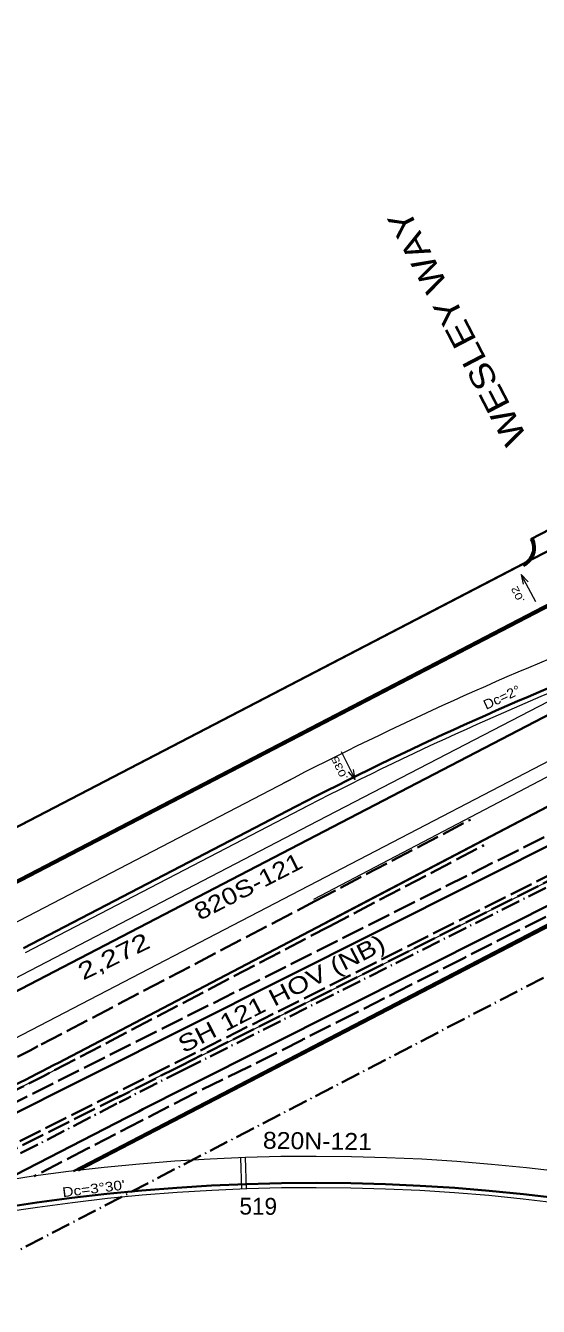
# Model space of a CAD drawing. Extents: x 2354993 to 2372084, y 6966390 to 6990057.
# Drawn here: x 2363006 to 2363431, y 6978118 to 6979180 of the extents above; entities that cross this region are included whole.
import ezdxf
from ezdxf.enums import TextEntityAlignment as Align

# ---------------------------------------------------------------- set-up
doc = ezdxf.new("R2010")
doc.units = 0
doc.header["$LTSCALE"] = 3.2
doc.linetypes.add('DOT_DASHED', pattern=[7.7, 5, -1.2, 0.3, -1.2])
doc.linetypes.add('LONG_DASHED', pattern=[7.5, 6, -1.5])
for name, color, linetype, lineweight in [('13', 7, 'Continuous', 13), ('17', 7, 'Continuous', 13), ('19', 7, 'Continuous', 13), ('2', 7, 'Continuous', 35), ('4', 7, 'Continuous', 13), ('5', 7, 'Continuous', 35), ('6', 7, 'Continuous', 35), ('9', 7, 'Continuous', 13)]:
    doc.layers.add(name, color=color, linetype=linetype, lineweight=lineweight)

msp = doc.modelspace()

# ---------------------------------------------------------------- linework, layer by layer
at = {"layer": '17'}
for p, q in [((2363268.695, 6978481.439), (2363677.359, 6978693.821)), ((2363183.998, 6978240.992), (2363184.891, 6978215.034)), ((2363187.996, 6978241.129), (2363188.889, 6978215.172))]:
    msp.add_line(p, q, dxfattribs=at)
at = {"layer": '19'}
for p, q in [((2363417.054, 6978724.995), (2363418.784, 6978716.872)), ((2363417.054, 6978724.995), (2363422.81, 6978719)), ((2363429.128, 6978702.214), (2363417.054, 6978724.995)), ((2363267.755, 6978578.025), (2363279.347, 6978554.995)), ((2363279.347, 6978554.995), (2363273.719, 6978561.11)), ((2363279.347, 6978554.995), (2363277.788, 6978563.153))]:
    msp.add_line(p, q, dxfattribs=at)
at = {"layer": '2'}
for p, q in [((2363038.234, 6978322.559), (2364007.4, 6978830.292)), ((2358006.591, 6975920.846), (2363488.891, 6978770.331)), ((2362811.106, 6978184.667), (2363604.71, 6978582.7)), ((2363003.914, 6978414.83), (2363230.047, 6978532.352)), ((2363143.211, 6978301.576), (2363589.111, 6978525.607)), ((2362988.207, 6978222.005), (2363089.737, 6978274.358))]:
    msp.add_line(p, q, dxfattribs=at)
at = {"layer": '2', "linetype": 'LONG_DASHED'}
for p, q in [((2362775.435, 6978175.726), (2363601.123, 6978589.851)), ((2363618.55, 6978565.019), (2362905.562, 6978206.794)), ((2363135.13, 6978317.66), (2363581.03, 6978541.691)), ((2363245.903, 6978453.932), (2363374.908, 6978521.516)), ((2363257.039, 6978432.672), (2363386.045, 6978500.257)), ((2363018.694, 6978334.9), (2363245.903, 6978453.932)), ((2363458.934, 6978451.609), (2363414.156, 6978429.36)), ((2363029.83, 6978313.64), (2363257.039, 6978432.672)), ((2363414.13, 6978429.346), (2363369.523, 6978406.758)), ((2363369.523, 6978406.757), (2363324.916, 6978384.169)), ((2363324.916, 6978384.168), (2363280.309, 6978361.58)), ((2363280.309, 6978361.579), (2363235.702, 6978338.991)), ((2363235.702, 6978338.99), (2363191.095, 6978316.402)), ((2363191.154, 6978316.43), (2363146.169, 6978294.605)), ((2363146.082, 6978294.561), (2363101.663, 6978271.606)), ((2363084.717, 6978292.33), (2362920.65, 6978209.898)), ((2363101.663, 6978271.606), (2363057.244, 6978248.651)), ((2363057.244, 6978248.651), (2363012.825, 6978225.696))]:
    msp.add_line(p, q, dxfattribs=at)
at = {"layer": '2'}
for centre, radius, start, end in [((2364544.669, 6976002.774), 2850.789, 111.22127, 117.46089), ((2365709.196, 6973194.37), 5715.578, 116.67607, 117.27757)]:
    msp.add_arc(centre, radius, start, end, dxfattribs=at)
at = {"layer": '2', "linetype": 'LONG_DASHED'}
for centre, radius, start, end in [((2361957.93, 6980359.697), 2285.831, 293.48147, 297.64944), ((2361957.927, 6980359.696), 2309.831, 293.48137, 297.6495), ((2365709.196, 6973194.37), 5733.578, 116.67607, 117.27757)]:
    msp.add_arc(centre, radius, start, end, dxfattribs=at)
at = {"layer": '4'}
msp.add_line((2362757.154, 6978215.587), (2363268.695, 6978481.438), dxfattribs=at)
at = {"layer": '5'}
for p, q in [((2363255.18, 6978436.214), (2364007.4, 6978830.292)), ((2363425.177, 6978754.243), (2363463.775, 6978774.478)), ((2362087.371, 6978041.876), (2363419.143, 6978734.078)), ((2362654.988, 6978292.473), (2363507.292, 6978735.395)), ((2362655.626, 6978291.114), (2363508.018, 6978734.082)), ((2362391.142, 6978063.692), (2363583.984, 6978683.611)), ((2363620.009, 6978528.496), (2363045.424, 6978230.005)), ((2363620.695, 6978527.162), (2363049.66, 6978230.516))]:
    msp.add_line(p, q, dxfattribs=at)
at = {"layer": '5', "lineweight": 13}
for p, q in [((2363244.971, 6978455.701), (2363891.715, 6978794.521)), ((2363248.405, 6978520.48), (2363498.513, 6978650.46)), ((2362993.757, 6978434.346), (2363229.499, 6978556.861)), ((2363135.13, 6978317.66), (2363581.03, 6978541.691)), ((2363005.748, 6978411.277), (2363241.489, 6978533.791)), ((2362329.78, 6978043.07), (2363248.405, 6978520.479))]:
    msp.add_line(p, q, dxfattribs=at)
at = {"layer": '5'}
for centre, radius, start, end in [((2363412.177, 6978747.044), 14.86, 294.19474, 28.97554), ((2363412.177, 6978747.044), 16.36, 294.19474, 28.97554), ((2361968.189, 6980365.073), 2305.831, 293.48164, 297.64942), ((2363244.672, 6976597.082), 1623.014, 38.12295, 103.3303)]:
    msp.add_arc(centre, radius, start, end, dxfattribs=at)
at = {"layer": '5', "lineweight": 13}
for centre, radius, start, end in [((2364544.669, 6976002.774), 2872.789, 111.22127, 117.46089), ((2364544.669, 6976002.774), 2846.789, 111.22127, 117.46089), ((2361968.189, 6980365.073), 2309.831, 293.48164, 297.64942), ((2365709.196, 6973194.37), 5733.578, 116.67607, 117.27757), ((2363244.672, 6976597.082), 1645.014, 38.12295, 103.3303), ((2363244.672, 6976597.082), 1619.014, 38.12295, 103.3303)]:
    msp.add_arc(centre, radius, start, end, dxfattribs=at)
at = {"layer": '6', "linetype": 'DOT_DASHED'}
for p, q in [((2363136.926, 6978314.086), (2363582.826, 6978538.117)), ((2360272.717, 6976747.357), (2363548.144, 6978448.903)), ((2360272.718, 6976747.358), (2363548.137, 6978448.9)), ((2360272.718, 6976747.358), (2363548.137, 6978448.9)), ((2362716.922, 6978097.869), (2363083.321, 6978286.801))]:
    msp.add_line(p, q, dxfattribs=at)
msp.add_arc((2365709.196, 6973194.37), 5729.578, 116.67607, 117.27757, dxfattribs=at)
at = {"layer": '9'}
msp.add_arc((2360722.521, 6984327.136), 5729.573, 359.50797, 359.50797, dxfattribs=at)

# ---------------------------------------------------------------- texts
at = {"layer": '13', "width": 1.2}
msp.add_text('WESLEY WAY', height=20, rotation=117.447, dxfattribs=at).set_placement((2363372.707, 6978934.43), align=Align.CENTER)
at = {"layer": '13'}
for s, rotation, width, p in [('820S-121', 27.223, 1.2, (2363150.343, 6978437.629)), ('2,272', 26.014, 1.35, (2363053.466, 6978387.998)), ('SH 121 HOV (NB)', 27.223, 1.25, (2363136.887, 6978327.523)), ('820N-121', 359.235, 1.1, (2363202.628, 6978248.531))]:
    msp.add_text(s, height=14, rotation=rotation, dxfattribs=dict(at, width=width)).set_placement(p)
msp.add_text('519', height=14, rotation=359.616, dxfattribs=at).set_placement((2363183.176, 6978193.859))
at = {"layer": '17'}
for s, height, rotation, width, p in [('Dc=2°', 7.999, 24.802, 1.1, (2363387.985, 6978612.641)), ("Dc=3°30'", 8, 7.036, 1.2, (2363036.778, 6978208.259))]:
    msp.add_text(s, height=height, rotation=rotation, dxfattribs=dict(at, width=width)).set_placement(p)
at = {"layer": '19'}
for s, height, rotation, width, p in [('.02', 6, 117.046, 1.3, (2363420.257, 6978703.128)), ('.035', 5.999, 115.33, 1.35, (2363273.564, 6978555.991))]:
    msp.add_text(s, height=height, rotation=rotation, dxfattribs=dict(at, width=width)).set_placement(p)

doc.saveas('drawing.dxf')
